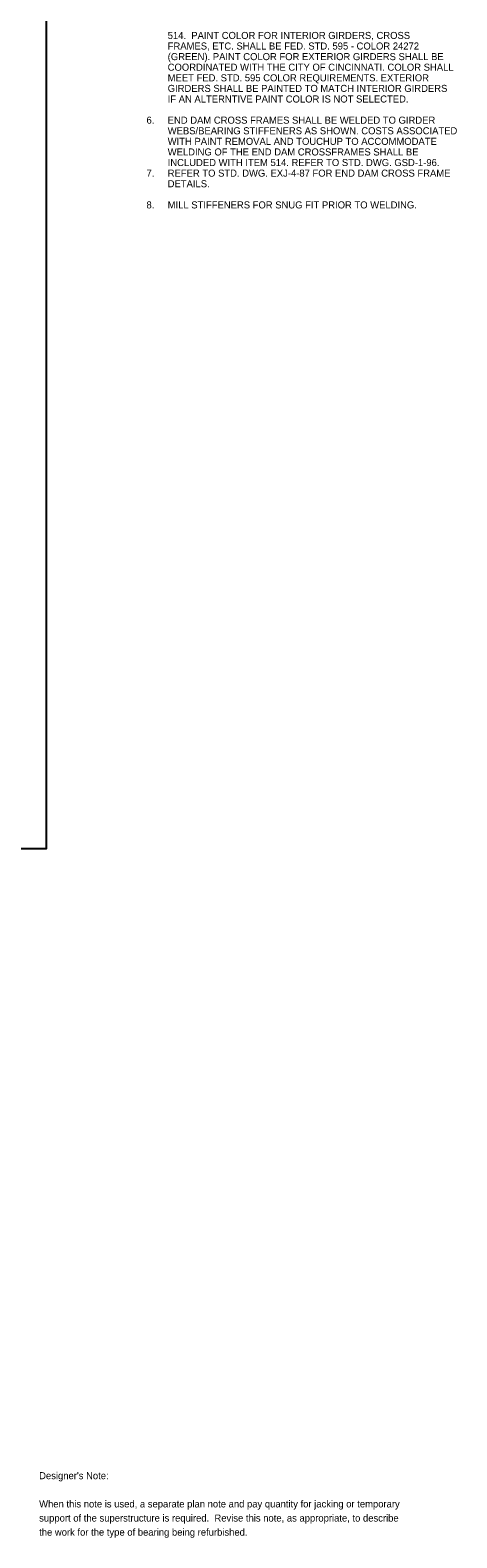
# Model space of a CAD drawing. Extents: x -11.4 to 74.5, y -13.7 to 46.2.
# Drawn here: x 33.68 to 42.14, y -13.67 to 16.23 of the extents above; entities that cross this region are included whole.
import ezdxf

# ---------------------------------------------------------------- set-up
doc = ezdxf.new("R2010")
doc.units = 0
for name, color, linetype in [('BR_P_Gen_Text', 7, 'Continuous'), ('SH_Cut_Line', 7, 'Continuous'), ('SH_Text', 7, 'Continuous')]:
    doc.layers.add(name, color=color, linetype=linetype)

msp = doc.modelspace()

# ---------------------------------------------------------------- linework, layer by layer
at = {"layer": 'SH_Cut_Line'}
msp.add_lwpolyline([(0, 0), (34, 0), (34, 22), (0, 22)], close=True, dxfattribs=at)

# ---------------------------------------------------------------- texts
at = {"layer": 'BR_P_Gen_Text'}
for s, p in [('514.  PAINT COLOR FOR INTERIOR GIRDERS, CROSS ', (36.406, 16.052)), ('FRAMES, ETC. SHALL BE FED. STD. 595 - COLOR 24272 ', (36.406, 15.842)), ('COORDINATED WITH THE CITY OF CINCINNATI. COLOR SHALL ', (36.406, 15.422)), ('(GREEN). PAINT COLOR FOR EXTERIOR GIRDERS SHALL BE ', (36.406, 15.632)), ('MEET FED. STD. 595 COLOR REQUIREMENTS. EXTERIOR ', (36.406, 15.212)), ('GIRDERS SHALL BE PAINTED TO MATCH INTERIOR GIRDERS ', (36.406, 15.002)), ('IF AN ALTERNTIVE PAINT COLOR IS NOT SELECTED.', (36.406, 14.792)), ('6.', (35.986, 14.372)), ('END DAM CROSS FRAMES SHALL BE WELDED TO GIRDER ', (36.406, 14.372)), ('WEBS/BEARING STIFFENERS AS SHOWN. COSTS ASSOCIATED ', (36.406, 14.162)), ('WITH PAINT REMOVAL AND TOUCHUP TO ACCOMMODATE ', (36.406, 13.952)), ('WELDING OF THE END DAM CROSSFRAMES SHALL BE ', (36.406, 13.742)), ('7.', (35.986, 13.322)), ('REFER TO STD. DWG. EXJ-4-87 FOR END DAM CROSS FRAME ', (36.406, 13.322)), ('INCLUDED WITH ITEM 514. REFER TO STD. DWG. GSD-1-96. ', (36.406, 13.532)), ('DETAILS.', (36.406, 13.112)), ('8.', (35.986, 12.692)), ('MILL STIFFENERS FOR SNUG FIT PRIOR TO WELDING.', (36.406, 12.692))]:
    msp.add_text(s, height=0.14, dxfattribs=at).set_placement(p)
at = {"layer": 'SH_Text'}
for s, p in [("Designer's Note:", (33.857, -12.503)), ('When this note is used, a separate plan note and pay quantity for jacking or temporary', (33.857, -13.063)), ('support of the superstructure is required.  Revise this note, as appropriate, to describe', (33.857, -13.343)), ('the work for the type of bearing being refurbished.', (33.857, -13.623))]:
    msp.add_text(s, height=0.14, dxfattribs=at).set_placement(p)

doc.saveas('drawing.dxf')
